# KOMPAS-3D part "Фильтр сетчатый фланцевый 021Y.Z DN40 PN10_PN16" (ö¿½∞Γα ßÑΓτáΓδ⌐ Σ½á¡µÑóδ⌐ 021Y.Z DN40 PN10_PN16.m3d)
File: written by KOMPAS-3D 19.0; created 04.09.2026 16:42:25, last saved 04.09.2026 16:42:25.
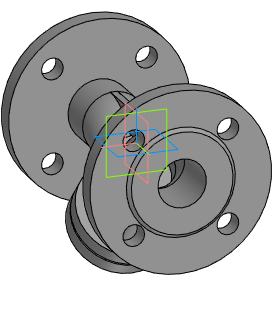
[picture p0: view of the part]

Document properties: Автор: Энергия; Полное имя файла: Z:\3.Личные\sachek\Dendor\_3D для проектировщиков\8.1 Фильтр сетчатый 021Y.Z\021Y.Z_STP\Фильтр сетчатый фланцевый 021Y.Z DN40 PN10_PN16.m3d

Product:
- Part/product: Фильтр сетчатый фланцевый 021Y.Z DN40 PN10_PN16

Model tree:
1. Операция без истории:1  (labels: Фильтр сетчатый фланцевый 021Y.Z DN40 PN10_PN16)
